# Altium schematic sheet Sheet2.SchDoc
size A4; CompanyName: Ultimaker; Revision: rev. 2.0.2
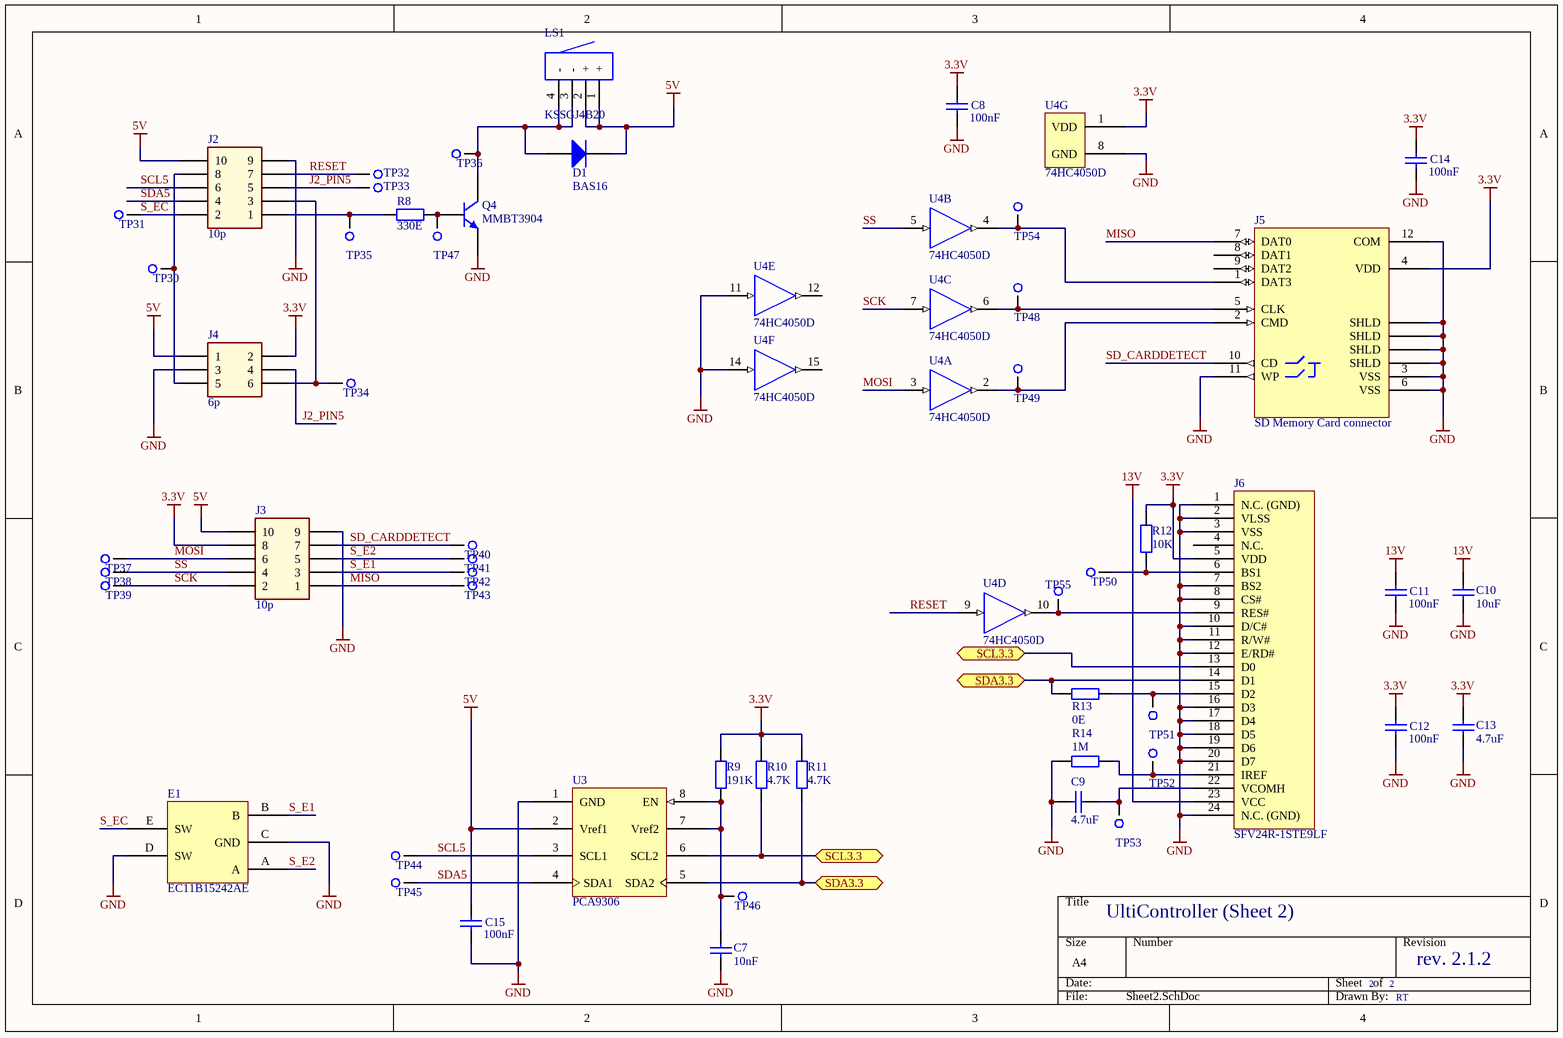
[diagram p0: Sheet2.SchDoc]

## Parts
C7  10nF  [C0805 (2012)]
C8  100nF  [C0805 (2012)]
C9  4.7uF  [C1206 (3216)]
C10  10uF  [C1206 (3216)]
C11  100nF  [C0805 (2012)]
C12  100nF  [C0805 (2012)]
C13  4.7uF  [C1206 (3216)]
C14  100nF  [C0805 (2012)]
C15  100nF  [C0805 (2012)]
D1  BAS16  [IC SOT23]
E1  EC11B15242AE  [Misc EC11B15242AE]
J2  10p  [HEADER 10P right angle]
J3  10p  [HEADER 10P right angle]
J4  6p  [HEADER 6P RIGHT ANGLE]
J5  SD Memory Card connector  [CON SD-Card]
J6  SFV24R-1STE9LF  [Con SFV24R-1STE9LF]
LS1  KSSGJ4B20  [Buzzer KSSGJ4B20]
Q4  MMBT3904  [IC SOT23]
R8  330E  [R0805 (2012)]
R9  191K  [R0805 (2012)]
R10  4.7K  [R0805 (2012)]
R11  4.7K  [R0805 (2012)]
R12  10K  [R0805 (2012)]
R13  0E  [R0805 (2012)]
R14  1M  [R0805 (2012)]
TP30  2mm  [TESTPOINT 2mm]  (value not drawn)  (no BOM)
TP31  2mm  [TESTPOINT 2mm]  (value not drawn)  (no BOM)
TP32  2mm  [TESTPOINT 2mm]  (value not drawn)  (no BOM)
TP33  2mm  [TESTPOINT 2mm]  (value not drawn)  (no BOM)
TP34  2mm  [TESTPOINT 2mm]  (value not drawn)  (no BOM)
TP35  2mm  [TESTPOINT 2mm]  (value not drawn)  (no BOM)
TP36  2mm  [TESTPOINT 2mm]  (value not drawn)  (no BOM)
TP37  2mm  [TESTPOINT 2mm]  (value not drawn)  (no BOM)
TP38  2mm  [TESTPOINT 2mm]  (value not drawn)  (no BOM)
TP39  2mm  [TESTPOINT 2mm]  (value not drawn)  (no BOM)
TP40  2mm  [TESTPOINT 2mm]  (value not drawn)  (no BOM)
TP41  2mm  [TESTPOINT 2mm]  (value not drawn)  (no BOM)
TP42  2mm  [TESTPOINT 2mm]  (value not drawn)  (no BOM)
TP43  2mm  [TESTPOINT 2mm]  (value not drawn)  (no BOM)
TP44  2mm  [TESTPOINT 2mm]  (value not drawn)  (no BOM)
TP45  2mm  [TESTPOINT 2mm]  (value not drawn)  (no BOM)
TP46  2mm  [TESTPOINT 2mm]  (value not drawn)  (no BOM)
TP47  2mm  [TESTPOINT 2mm]  (value not drawn)  (no BOM)
TP48  2mm  [TESTPOINT 2mm]  (value not drawn)  (no BOM)
TP49  2mm  [TESTPOINT 2mm]  (value not drawn)  (no BOM)
TP50  2mm  [TESTPOINT 2mm]  (value not drawn)  (no BOM)
TP51  2mm  [TESTPOINT 2mm]  (value not drawn)  (no BOM)
TP52  2mm  [TESTPOINT 2mm]  (value not drawn)  (no BOM)
TP53  2mm  [TESTPOINT 2mm]  (value not drawn)  (no BOM)
TP54  2mm  [TESTPOINT 2mm]  (value not drawn)  (no BOM)
TP55  2mm  [TESTPOINT 2mm]  (value not drawn)  (no BOM)
U3  PCA9306  [IC SSOP-8]
U4  74HC4050D  [IC SOIC-16]  (parts A,B,C,D,E,F,G of 7)

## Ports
SCL3.3 (bidir), SDA3.3 (bidir)

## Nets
3.3V: C8.2 C12.2 C13.1 C14.2 J3.8 J4.2 J5.4(VDD) J6.5(VDD) R9.2 R10.2 R11.2 R12.2 U4.1(VDD)
5V: C15.2 D1.3(K) J2.10 J3.10 J4.1 LS1.1(+) LS1.2(+) U3.2(Vref1)
13V: C10.2 C11.2 J6.23(VCC)
GND: C7.1 C8.1 C9.2 C10.1 C11.1 C12.1 C13.2 C14.1 C15.1 E1.C(GND) E1.D(SW) J2.9 J3.9 J4.3 J5.3(VSS) J5.6(VSS) J5.11(WP) J5.12(COM) J5.A(SHLD) J5.B(SHLD) J5.C(SHLD) J5.D(SHLD) J6.1(N.C._(GND)) J6.2(VLSS) J6.3(VSS) J6.7(BS2) J6.8(CS#) J6.10(D/C#) J6.11(R/W#) J6.12(E/RD#) J6.16(D3) J6.17(D4) J6.18(D5) J6.19(D6) J6.20(D7) J6.24(N.C._(GND)) Q4.2(E) R14.1 U3.1(GND) U4.8(GND) U4.11(A) U4.14(A)
J2_PIN5: J2.5 J4.4 TP33.1
MISO: J3.1 J5.7(DAT0) TP43.1
MOSI: J3.6 TP37.1 U4.3(A)
RESET: J2.7 TP32.1 U4.9(A)
S_E1: E1.B J3.3 TP42.1
S_E2: E1.A J3.5 TP41.1
S_EC: E1.E(SW) J2.2 TP31.1
SCK: J3.2 TP39.1 U4.7(A)
SCL3.3: J6.13(D0) R10.1 U3.6(SCL2) ; port SCL3.3
SCL5: J2.6 TP44.1 U3.3(SCL1)
SD_CARDDETECT: J3.7 J5.10(CD) TP40.1
SDA3.3: J6.14(D1) R11.1 R13.1 U3.5(SDA2) ; port SDA3.3
SDA5: J2.4 TP45.1 U3.4(SDA1)
SS: J3.4 TP38.1 U4.5(A)
NetC7_2: C7.2 R9.1 TP46.1 U3.7(Vref2) U3.8(EN)
NetC9_1: C9.1 J6.22(VCOMH) TP53.1
NetD1_1: D1.1(A) LS1.3(-) LS1.4(-) Q4.3(C) TP36.1
NetJ2_1: J2.1 R8.1 TP35.1
NetJ2_3: J2.3 J4.6 TP34.1
NetJ2_8: J2.8 J4.5 TP30.1
NetJ5_1: J5.1(DAT3) TP54.1 U4.4(Y)
NetJ5_2: J5.2(CMD) TP49.1 U4.2(Y)
NetJ5_5: J5.5(CLK) TP48.1 U4.6(Y)
NetJ6_6: J6.6(BS1) R12.1 TP50.1
NetJ6_9: J6.9(RES#) TP55.1 U4.10(Y)
NetJ6_15: J6.15(D2) R13.2 TP51.1
NetJ6_21: J6.21(IREF) R14.2 TP52.1
NetQ4_1: Q4.1(B) R8.2 TP47.1

Not connected (* = marked no-connect by the designer): J5 8(DAT1) 9(DAT2); J6 4(N.C.); U4 12(Y) 15(Y)

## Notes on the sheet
- UltiController (Sheet 2)
- 2
- rev. 2.1.2
- RT

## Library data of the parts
C7 = Cap 10nF X7R 0805: Cap 10nF X7R 0805 10% 100V; Mfg: AVX; Mfg code: 08051C103K4Z2A
C8 C11 C12 C14 C15 = Cap 100nF X7R 0805: Cap 100nF X7R 0805 10% 100V; Mfg: AVX; Mfg code: 08051C104K4T2A
C9 C13 = Cap 4.7uF X7R 1206: Cap 4.7uF 1206 X7R 10% 25V; Mfg: TDK; Mfg code: C3216X7R1E475K160AC
C10 = Cap 10uF X7R 1206: Cap 10uF 1206 X7R 10% 25V; Mfg: KEMET; Mfg code: C1206C106K3RAC TU
D1 = Diode BAS16: Diode BAS16  SOT23 85V 215MA; Mfg: NXP
E1 = Misc EC11B15242AE: Misc EC11B15242AE encoder horiz; Mfg: ALPS
J2 J3 = Header 10p: Header 2x5p right angle 2.54mm; Mfg: WURTH ELEKTRONIK; Mfg code: 61201021721
J4 = Header 6p r.a.: Header 2x3p right angle 2.54mm; Mfg: FCI; Mfg code: 68021-206HLF
J5 = Connector SD-Card-Hirose: Connector Std,reverse SD Memory Card connector; Faber ItemCode: 36966100; Mfg: HRS (HIROSE); Mfg code: DM1AA-SF-PEJ(72); Faber Artikelomschrijving: SD-KAARDHOUDER SMD DM1AA-SF-PEJ(72) HIROSE; Bestel grote: 1; Prijs: 3,02
J6 = Connector SFV24R-1STE9LF: Connector FPC/FFC 0.5mm R/A 24p SMD; Mfg: FCI
LS1 = Buzzer KSSGJ4B20: Buzzer KSSGJ4B20 SMD; Mfg: KINGSTATE
Q4 = NPN MMBT3904: NPN MMBT3904 SOT-23 200mA; Mfg: NXP; Mfg code: MMBT3904,215
R8 = Res 330E 0805: Res 330E 0805 1% 100mW; Mfg: MULTICOMP; Mfg code: MC 0.1W 0805 1% 330R
R9 = Res 191K 0805: Res 191K 0805 1% 125mW; Mfg: VISHAY DRALORIC; Mfg code: CRCW0805191KFKEA
R10 R11 = Res 4.7K 0805: Res 4.7K 0805 1% 100mW; Mfg: MULTICOMP; Mfg code: MC 0.1W 0805 1% 4K7
R12 = Res 10K 0805: Res 10K 0805 1% 100mW; Mfg: MULTICOMP; Mfg code: MC 0.1W 0805 1% 10K
R13 = Res 0E 0805: Res 0E 0805 1% 100mW; Mfg: MULTICOMP; Mfg code: MC 0.1W 0805 0R
R14 = Res 1M 0805: Res 1M 0805 1% 100mW; Mfg: MULTICOMP; Mfg code: MC 0.1W 0805 1% 1M
TP30-TP55 = Testpoint, 2mm, round: Remarks: Not a component
U3 = IC PCA9306: IC PCA9306 Voltage Level translator; Mfg: TEXAS INSTRUMENTS; Mfg code: PCA9306DCTR
U4 = IC 74HC4050D: IC Hex Non-Inverting Buffer/Logic-Level Down Converter; Faber ItemCode: 35592900; Mfg: NXP; Faber Artikelomschrijving: IC 74HC4050D SO-16 NXP; Bestel grote: 2500; Prijs: 0,0878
